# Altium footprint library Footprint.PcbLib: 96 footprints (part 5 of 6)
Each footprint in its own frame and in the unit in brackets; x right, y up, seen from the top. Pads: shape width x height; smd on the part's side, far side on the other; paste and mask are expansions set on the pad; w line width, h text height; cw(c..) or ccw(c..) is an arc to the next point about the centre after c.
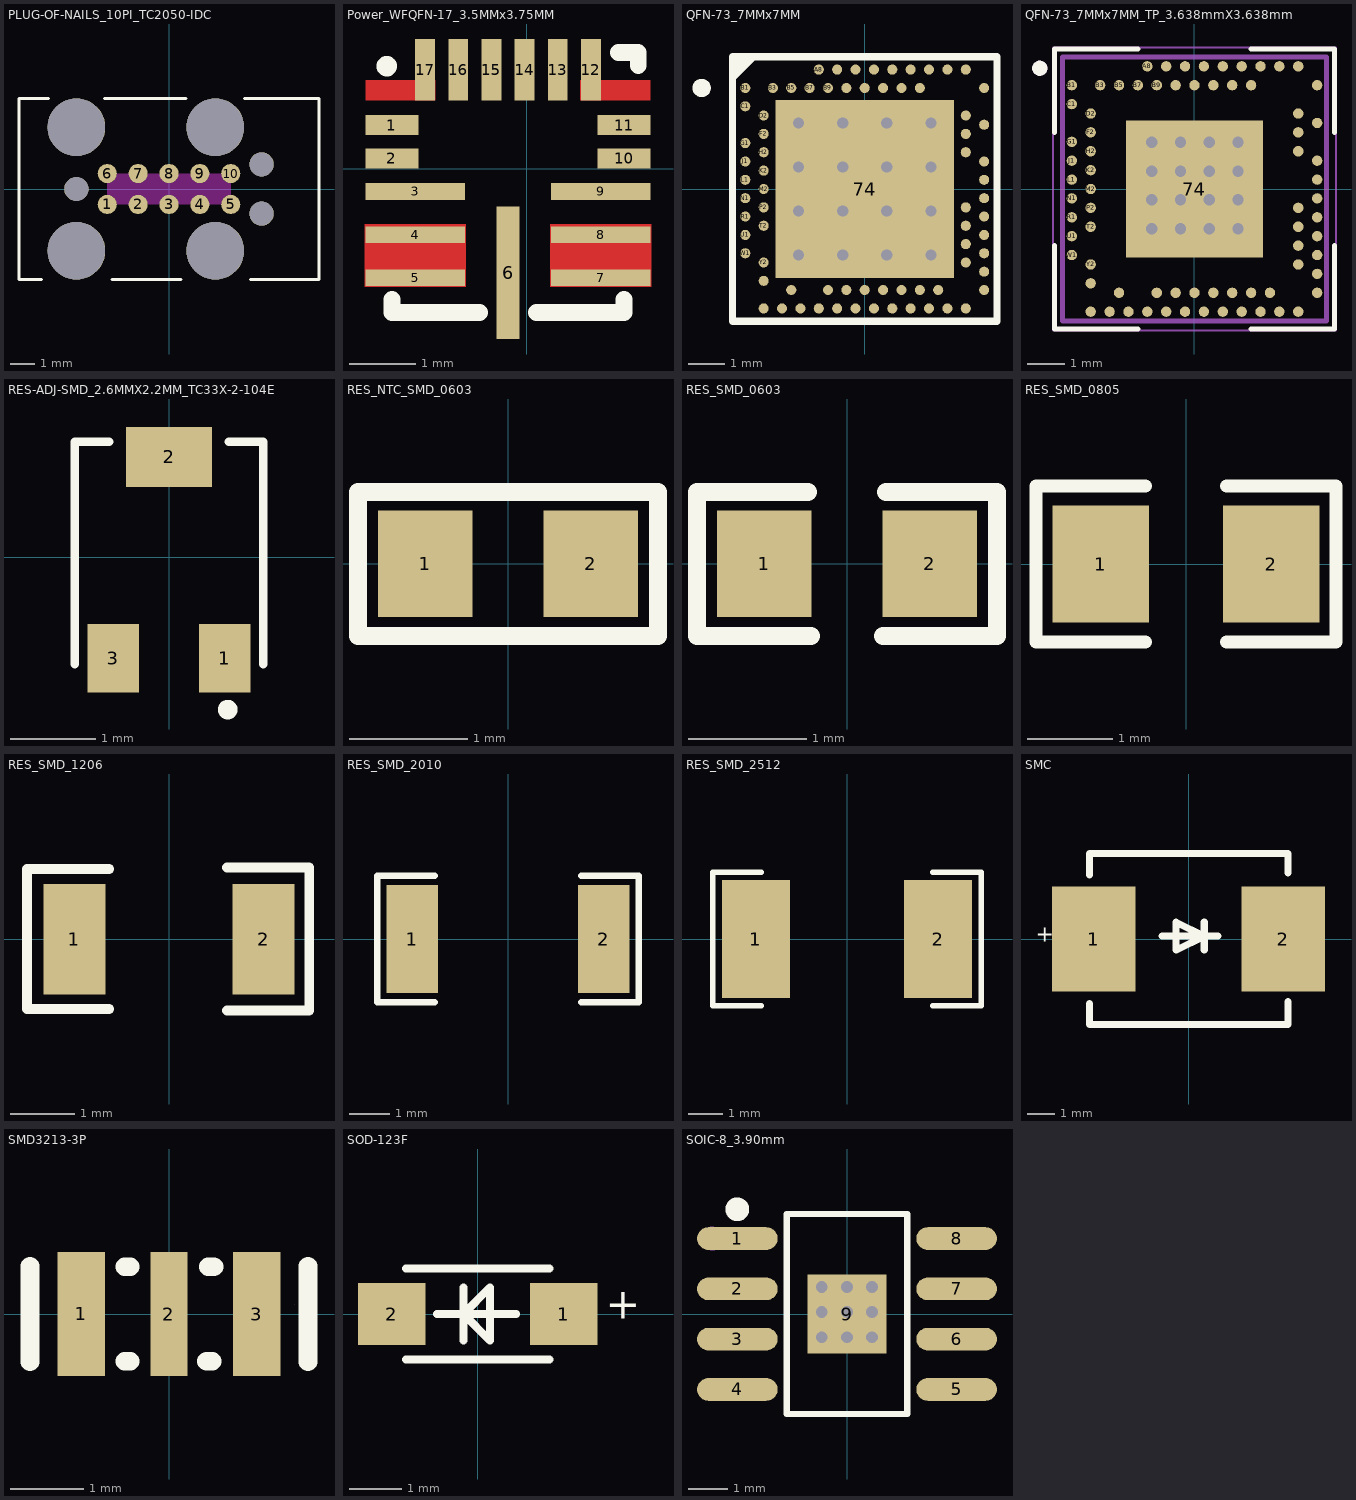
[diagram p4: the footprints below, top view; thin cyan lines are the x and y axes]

## PLUG-OF-NAILS_10PI_TC2050-IDC [mil]
pads (17):
  round 31 smd paste-39.37: 1(-100,-25) 2(-50,-25) 3(0,-25) 4(50,-25) 5(100,-25) 6(-100,25) 7(-50,25) 8(0,25) 9(50,25) 10(100,25)
  round 93.5 hole 93.5 unplated: ""(-150,-100) ""(-150,100) ""(75,-100) ""(75,100)
  round 39 hole 39 unplated: ""(-150,0) ""(150,-39.96) ""(150,39.96)
Top Overlay:
  lines w5: -206.69,-146.77 -242.91,-146.77 -242.91,146.77 -194.88,146.77 ; -104.33,146.77 27.56,146.77 ; -92.52,-146.77 19.68,-146.77 ; 122.05,146.77 242.91,146.77 242.91,-146.77 131.89,-146.77
Keep-Out Layer:
  drawing of 17 lines, arcs and shapes, not listed

## Power_WFQFN-17_3.5MMx3.75MM [mm]
pads (17):
  rect 0.8x0.3 smd paste+0 mask+0.05: 1(-2.029,0.66) 2(-2.029,0.16) 10(1.471,0.16) 11(1.471,0.66)
  rect 1.5x0.25 smd paste+0 mask+0.05: 3(-1.679,-0.34) 4(-1.679,-0.99) 5(-1.679,-1.64) 7(1.121,-1.64) 8(1.121,-0.99) 9(1.121,-0.34)
  rect 0.35x2 smd paste+0 mask+0.05: 6(-0.279,-1.565)
  rect 0.3x0.925 smd paste+0 mask+0.05: 12(0.971,1.497) 13(0.471,1.497) 14(-0.029,1.497) 15(-0.529,1.497) 16(-1.029,1.497) 17(-1.529,1.497)
Top Layer:
  region: 0.356,-0.834 1.88,-0.834 1.88,-1.778 0.356,-1.778
  region: -2.438,-0.834 -0.914,-0.834 -0.914,-1.778 -2.438,-1.778
  region: 0.813,1.338 1.866,1.338 1.866,1.038 0.813,1.038
  region: -2.424,1.338 -1.374,1.338 -1.374,1.038 -2.424,1.038
Top Overlay:
  circle w0.254: c-2.108,1.549 r0.027
  lines w0.254: -2.029,-1.965 -2.029,-2.165 -0.711,-2.165 ; 0.152,-2.165 1.471,-2.165 1.471,-1.965 ; 1.386,1.758 1.686,1.758 1.686,1.558
3D body "MAXIM_90-100129.step": height 0.8, standoff 0, extent -2.105,-2.204 1.495,1.646

## QFN-73_7MMx7MM [mm]
pads (90):
  rect 4.85x4.85 smd paste-5 mask+0.05: 74(0,0)
  round 0.275 smd paste+0.012 mask+0.05: A8(-1.25,3.25) A10(-0.75,3.25) A12(-0.25,3.25) A14(0.25,3.25) A16(0.75,3.25) A18(1.25,3.25) A20(1.75,3.25) A22(2.25,3.25) A23(2.75,3.25) AA24(3.25,-2.25) AB2(-2.75,-2.5) AC5(-2,-2.75) AC9(-1,-2.75) AC11(-0.5,-2.75) AC13(0,-2.75) AC15(0.5,-2.75) AC17(1,-2.75) AC19(1.5,-2.75) AC21(2,-2.75) AC24(3.25,-2.75) AD2(-2.75,-3.25) AD4(-2.25,-3.25) AD6(-1.75,-3.25) AD8(-1.25,-3.25) AD10(-0.75,-3.25) AD12(-0.25,-3.25) AD14(0.25,-3.25) AD16(0.75,-3.25) AD18(1.25,-3.25) AD20(1.75,-3.25) AD22(2.25,-3.25) AD23(2.75,-3.25) B1(-3.25,2.75) B3(-2.5,2.75) B5(-2,2.75) B7(-1.5,2.75) B9(-1,2.75) B11(-0.5,2.75) B13(0,2.75) B15(0.5,2.75) B17(1,2.75) B19(1.5,2.75) B24(3.25,2.75) C1(-3.25,2.25) D2(-2.75,2) D23(2.75,2) E24(3.25,1.75) F2(-2.75,1.5) F23(2.75,1.5) G1(-3.25,1.25) H2(-2.75,1) H23(2.75,1) J1(-3.25,0.75) J24(3.25,0.75) K2(-2.75,0.5) L1(-3.25,0.25) L24(3.25,0.25) M2(-2.75,0) N1(-3.25,-0.25) N24(3.25,-0.25) P2(-2.75,-0.5) P23(2.75,-0.5) R1(-3.25,-0.75) R24(3.25,-0.75) T2(-2.75,-1) T23(2.75,-1) U1(-3.25,-1.25) U24(3.25,-1.25) V23(2.75,-1.5) W1(-3.25,-1.75) W24(3.25,-1.75) Y2(-2.75,-2) Y23(2.75,-2)
  rrect50% 0.94x0.94 on Top Paste: ""(-1.71,-1.71) ""(-1.71,-0.57) ""(-1.71,0.57) ""(-1.71,1.71) ""(-0.57,-1.71) ""(-0.57,-0.57) ""(-0.57,0.57) ""(-0.57,1.71) ""(0.57,-1.71) ""(0.57,-0.57) ""(0.57,0.57) ""(0.57,1.71) ""(1.71,-1.71) ""(1.71,-0.57) ""(1.71,0.57) ""(1.71,1.71)
via 1.8,-1.8 diameter 0.61 hole 0.305
via 0.6,-1.8 diameter 0.61 hole 0.305
via -0.6,-1.8 diameter 0.61 hole 0.305
via -1.8,-1.8 diameter 0.61 hole 0.305
via 1.8,-0.6 diameter 0.61 hole 0.305
via 0.6,-0.6 diameter 0.61 hole 0.305
via -0.6,-0.6 diameter 0.61 hole 0.305
via -1.8,-0.6 diameter 0.61 hole 0.305
via 1.8,0.6 diameter 0.61 hole 0.305
via 0.6,0.6 diameter 0.61 hole 0.305
via -0.6,0.6 diameter 0.61 hole 0.305
via -1.8,0.6 diameter 0.61 hole 0.305
via 1.8,1.8 diameter 0.61 hole 0.305
via 0.6,1.8 diameter 0.61 hole 0.305
via -0.6,1.8 diameter 0.61 hole 0.305
via -1.8,1.8 diameter 0.61 hole 0.305
Top Overlay:
  circle w0.25: c-4.44,2.75 r0.125
  region: -3,3.5 -3.5,3 -3.5,3.5
  lines w0.2: -3.6,-3.6 3.6,-3.6 3.6,3.6 -3.6,3.6 -3.6,-3.6
3D body "LGA88C25P25X25_700X700X85.step": height 0.85, standoff 0, extent -3.55,-3.55 3.55,3.55

## QFN-73_7MMx7MM_TP_3.638mmX3.638mm [mm]
pads (74):
  rect 3.638x3.638 smd mask-0.01: 74(0,0)
  round 0.275 smd paste-1 mask+0: A8(-1.25,3.25) A10(-0.75,3.25) A12(-0.25,3.25) A14(0.25,3.25) A16(0.75,3.25) A18(1.25,3.25) A20(1.75,3.25) A22(2.25,3.25) A23(2.75,3.25) AA24(3.25,-2.25) AB2(-2.75,-2.5) AC5(-2,-2.75) AC9(-1,-2.75) AC11(-0.5,-2.75) AC13(0,-2.75) AC15(0.5,-2.75) AC17(1,-2.75) AC19(1.5,-2.75) AC21(2,-2.75) AC24(3.25,-2.75) AD2(-2.75,-3.25) AD4(-2.25,-3.25) AD6(-1.75,-3.25) AD8(-1.25,-3.25) AD10(-0.75,-3.25) AD12(-0.25,-3.25) AD14(0.25,-3.25) AD16(0.75,-3.25) AD18(1.25,-3.25) AD20(1.75,-3.25) AD22(2.25,-3.25) AD23(2.75,-3.25) B1(-3.25,2.75) B3(-2.5,2.75) B5(-2,2.75) B7(-1.5,2.75) B9(-1,2.75) B11(-0.5,2.75) B13(0,2.75) B15(0.5,2.75) B17(1,2.75) B19(1.5,2.75) B24(3.25,2.75) C1(-3.25,2.25) D2(-2.75,2) D23(2.75,2) E24(3.25,1.75) F2(-2.75,1.5) F23(2.75,1.5) G1(-3.25,1.25) H2(-2.75,1) H23(2.75,1) J1(-3.25,0.75) J24(3.25,0.75) K2(-2.75,0.5) L1(-3.25,0.25) L24(3.25,0.25) M2(-2.75,0) N1(-3.25,-0.25) N24(3.25,-0.25) P2(-2.75,-0.5) P23(2.75,-0.5) R1(-3.25,-0.75) R24(3.25,-0.75) T2(-2.75,-1) T23(2.75,-1) U1(-3.25,-1.25) U24(3.25,-1.25) V23(2.75,-1.5) W1(-3.25,-1.75) W24(3.25,-1.75) Y2(-2.75,-2) Y23(2.75,-2)
via -1.132,1.235 diameter 0.5 hole 0.3
via -1.132,0.473 diameter 0.5 hole 0.3
via -1.132,-0.289 diameter 0.5 hole 0.3
via -1.132,-1.051 diameter 0.5 hole 0.3
via -0.37,-1.051 diameter 0.5 hole 0.3
via -0.37,-0.289 diameter 0.5 hole 0.3
via -0.37,0.473 diameter 0.5 hole 0.3
via -0.37,1.235 diameter 0.5 hole 0.3
via 0.392,1.235 diameter 0.5 hole 0.3
via 0.392,0.473 diameter 0.5 hole 0.3
via 0.392,-0.289 diameter 0.5 hole 0.3
via 0.392,-1.051 diameter 0.5 hole 0.3
via 1.154,-1.051 diameter 0.5 hole 0.3
via 1.154,-0.289 diameter 0.5 hole 0.3
via 1.154,0.473 diameter 0.5 hole 0.3
via 1.154,1.235 diameter 0.5 hole 0.3
Top Overlay:
  circle w0.2: c-4.1,3.2 r0.1
  lines w0.127: -3.707,-1.5 -3.708,-3.707 -1.5,-3.707 ; -3.708,1.5 -3.708,3.708 -1.5,3.708 ; 1.5,-3.707 3.708,-3.707 3.708,-1.5 ; 1.5,3.708 3.708,3.708 3.707,1.5
Top Paste:
  circle w0.143: c-1.25,3.25 r0.072
  circle w0.143: c-0.75,3.25 r0.072
  circle w0.143: c-0.25,3.25 r0.072
  circle w0.143: c0.25,3.25 r0.072
  circle w0.143: c0.75,3.25 r0.072
  circle w0.143: c1.25,3.25 r0.072
  circle w0.143: c1.75,3.25 r0.072
  circle w0.143: c2.25,3.25 r0.072
  circle w0.143: c2.75,3.25 r0.072
  circle w0.143: c-2.5,2.75 r0.072
  circle w0.143: c-2,2.75 r0.072
  circle w0.143: c-1.5,2.75 r0.072
  circle w0.143: c-1,2.75 r0.072
  circle w0.143: c-0.5,2.75 r0.072
  circle w0.143: c0,2.75 r0.072
  circle w0.143: c0.5,2.75 r0.072
  circle w0.143: c1,2.75 r0.072
  circle w0.143: c1.5,2.75 r0.072
  circle w0.143: c-3.25,2.75 r0.072
  circle w0.143: c3.25,2.75 r0.072
  circle w0.143: c3.25,1.75 r0.072
  circle w0.143: c2.75,2 r0.072
  circle w0.143: c2.75,1.5 r0.072
  circle w0.143: c2.75,1 r0.072
  circle w0.143: c3.25,0.75 r0.072
  circle w0.143: c3.25,0.25 r0.072
  circle w0.143: c3.25,-0.25 r0.072
  circle w0.143: c3.25,-0.75 r0.072
  circle w0.143: c3.25,-1.25 r0.072
  circle w0.143: c3.25,-1.75 r0.072
  circle w0.143: c3.25,-2.25 r0.072
  circle w0.143: c3.25,-2.75 r0.072
  circle w0.143: c2.75,-2 r0.072
  circle w0.143: c2.75,-1.5 r0.072
  circle w0.143: c2.75,-1 r0.072
  circle w0.143: c2.75,-0.5 r0.072
  circle w0.143: c-3.25,2.25 r0.072
  circle w0.143: c-3.25,1.25 r0.072
  circle w0.143: c-3.25,0.75 r0.072
  circle w0.143: c-3.25,0.25 r0.072
  circle w0.143: c-3.25,-0.25 r0.072
  circle w0.143: c-3.25,-0.75 r0.072
  circle w0.143: c-3.25,-1.25 r0.072
  circle w0.143: c-3.25,-1.75 r0.072
  circle w0.143: c-2.75,2 r0.072
  circle w0.143: c-2.75,1.5 r0.072
  circle w0.143: c-2.75,1 r0.072
  circle w0.143: c-2.75,0.5 r0.072
  circle w0.143: c-2.75,0 r0.072
  circle w0.143: c-2.75,-0.5 r0.072
  circle w0.143: c-2.75,-1 r0.072
  circle w0.143: c-2.75,-2 r0.072
  circle w0.143: c-2.75,-2.5 r0.072
  circle w0.143: c-2.75,-3.25 r0.072
  circle w0.143: c-2.25,-3.25 r0.072
  circle w0.143: c-1.75,-3.25 r0.072
  circle w0.143: c-1.25,-3.25 r0.072
  circle w0.143: c-2,-2.75 r0.072
  circle w0.143: c-1,-2.75 r0.072
  circle w0.143: c-0.75,-3.25 r0.072
  circle w0.143: c-0.25,-3.25 r0.072
  circle w0.143: c0.25,-3.25 r0.072
  circle w0.143: c0.75,-3.25 r0.072
  circle w0.143: c1.25,-3.25 r0.072
  circle w0.143: c1.75,-3.25 r0.072
  circle w0.143: c2.25,-3.25 r0.072
  circle w0.143: c2.75,-3.25 r0.072
  circle w0.143: c2,-2.75 r0.072
  circle w0.143: c1.5,-2.75 r0.072
  circle w0.143: c1,-2.75 r0.072
  circle w0.143: c0.5,-2.75 r0.072
  circle w0.143: c0,-2.75 r0.072
  circle w0.143: c-0.5,-2.75 r0.072
Top Solder:
  circle w0.162: c-1.25,3.25 r0.081
  circle w0.162: c-0.75,3.25 r0.081
  circle w0.162: c-0.25,3.25 r0.081
  circle w0.162: c0.25,3.25 r0.081
  circle w0.162: c0.75,3.25 r0.081
  circle w0.162: c1.25,3.25 r0.081
  circle w0.162: c1.75,3.25 r0.081
  circle w0.162: c2.25,3.25 r0.081
  circle w0.162: c2.75,3.25 r0.081
  circle w0.162: c-2.5,2.75 r0.081
  circle w0.162: c-2,2.75 r0.081
  circle w0.162: c-1.5,2.75 r0.081
  circle w0.162: c-1,2.75 r0.081
  circle w0.162: c-0.5,2.75 r0.081
  circle w0.162: c0,2.75 r0.081
  circle w0.162: c0.5,2.75 r0.081
  circle w0.162: c1,2.75 r0.081
  circle w0.162: c1.5,2.75 r0.081
  circle w0.162: c-3.25,2.75 r0.081
  circle w0.162: c3.25,2.75 r0.081
  circle w0.162: c-3.25,2.25 r0.081
  circle w0.162: c-3.25,1.25 r0.081
  circle w0.162: c-3.25,0.75 r0.081
  circle w0.162: c-3.25,0.25 r0.081
  circle w0.162: c-3.25,-0.25 r0.081
  circle w0.162: c-3.25,-0.75 r0.081
  circle w0.162: c-3.25,-1.25 r0.081
  circle w0.162: c-3.25,-1.75 r0.081
  circle w0.162: c-2.75,-2 r0.081
  circle w0.162: c-2.75,-1 r0.081
  circle w0.162: c-2.75,-0.5 r0.081
  circle w0.162: c-2.75,0 r0.081
  circle w0.162: c-2.75,0.5 r0.081
  circle w0.162: c-2.75,1 r0.081
  circle w0.162: c-2.75,1.5 r0.081
  circle w0.162: c-2.75,2 r0.081
  circle w0.162: c3.25,1.75 r0.081
  circle w0.162: c2.75,2 r0.081
  circle w0.162: c2.75,1.5 r0.081
  circle w0.162: c2.75,1 r0.081
  circle w0.162: c3.25,0.75 r0.081
  circle w0.162: c3.25,0.25 r0.081
  circle w0.162: c3.25,-0.25 r0.081
  circle w0.162: c2.75,-0.5 r0.081
  circle w0.162: c2.75,-1 r0.081
  circle w0.162: c3.25,-0.75 r0.081
  circle w0.162: c3.25,-1.25 r0.081
  circle w0.162: c3.25,-1.75 r0.081
  circle w0.162: c2.75,-1.5 r0.081
  circle w0.162: c2.75,-2 r0.081
  circle w0.162: c3.25,-2.25 r0.081
  circle w0.162: c3.25,-2.75 r0.081
  circle w0.162: c2.75,-3.25 r0.081
  circle w0.162: c2.25,-3.25 r0.081
  circle w0.162: c1.75,-3.25 r0.081
  circle w0.162: c1.25,-3.25 r0.081
  circle w0.162: c0.75,-3.25 r0.081
  circle w0.162: c0.25,-3.25 r0.081
  circle w0.162: c-0.25,-3.25 r0.081
  circle w0.162: c-0.75,-3.25 r0.081
  circle w0.162: c-1.25,-3.25 r0.081
  circle w0.162: c-1.75,-3.25 r0.081
  circle w0.162: c-2.25,-3.25 r0.081
  circle w0.162: c-2.75,-3.25 r0.081
  circle w0.162: c-2,-2.75 r0.081
  circle w0.162: c-1,-2.75 r0.081
  circle w0.162: c-0.5,-2.75 r0.081
  circle w0.162: c0,-2.75 r0.081
  circle w0.162: c0.5,-2.75 r0.081
  circle w0.162: c1,-2.75 r0.081
  circle w0.162: c1.5,-2.75 r0.081
  circle w0.162: c2,-2.75 r0.081
  circle w0.162: c-2.75,-2.5 r0.081
Mechanical 13:
  circle w0.2: c-4.1,3.2 r0.1
  lines w0.127: -3.5,-3.5 3.5,-3.5 3.5,3.5 -3.5,3.5 -3.5,-3.5
Mechanical 15:
  lines w0.05: -3.75,-3.75 3.75,-3.75 3.75,3.75 -3.75,3.75 -3.75,-3.75
3D body "LGA88C25P25X25_700X700X85.step": height 0.85, standoff 0, extent -3.55,-3.55 3.55,3.55

## RES-ADJ-SMD_2.6MMX2.2MM_TC33X-2-104E [mm]
pads (3):
  rect 0.6x0.8 smd mask+0.04: 1(0.65,-1.175) 3(-0.65,-1.175)
  rect 1x0.7 smd mask+0.04: 2(0,1.175)
Top Overlay:
  circle w0.127: c0.686,-1.778 r0.051
  lines w0.1: -1.1,-1.25 -1.1,1.35 -0.7,1.35 ; 0.7,1.35 1.1,1.35 1.1,-1.25
3D body "TC42.stp": height 0.84, standoff 0.05, extent -1.079,-1.524 1.13,1.321

## RES_NTC_SMD_0603 [mm]
pads (2):
  rect 0.8x0.9 smd paste+0 mask+0.051: 1(-0.7,0) 2(0.7,0)
Top Overlay:
  lines w0.152: -1.27,-0.611 -1.27,0.608 1.27,0.608 1.27,-0.611 -1.245,-0.611
3D body "bf_0603_part.step": height 0.8, standoff 0, extent -0.8,-0.452 0.8,0.453

## RES_SMD_0402 [mm]

## RES_SMD_0603 [mm]
pads (2):
  rect 0.8x0.9 smd paste+0 mask+0.051: 1(-0.7,0) 2(0.7,0)
Top Overlay:
  lines w0.152: -0.33,0.608 -1.27,0.608 -1.27,-0.611 -0.305,-0.611 ; 0.305,-0.611 1.27,-0.611 1.27,0.608 0.33,0.608
3D body "User Library-CR1608-0603.step": height 0.45, standoff 0, extent -0.8,-0.4 0.8,0.4

## RES_SMD_0805 [mm]
pads (2):
  rect 1.133x1.377 smd paste-100 mask+0.051: 1(-1,0) 2(1,0)
Top Overlay:
  lines w0.152: -0.476,-0.917 -1.761,-0.917 -1.761,0.917 -0.476,0.917 ; 0.476,-0.917 1.761,-0.917 1.761,0.917 0.476,0.917
3D body "ESR10EZPJ100.step": height 0.65, standoff 0, extent -1.102,-0.574 0.898,0.676

## RES_SMD_1206 [mm]
pads (2):
  rect 0.97x1.73 smd: 1(-1.48,0) 2(1.48,0)
Top Overlay:
  lines w0.152: -0.933,-1.092 -2.218,-1.092 -2.218,1.095 -0.933,1.095 ; 0.908,-1.118 2.193,-1.118 2.193,1.12 0.908,1.12
3D body "step_temp.STEP": height 0.65, standoff 0, extent -1.55,-0.8 1.55,0.8

## RES_SMD_2010 [mm]
pads (2):
  rect 1.283x2.7 smd paste-100 mask+0.051: 1(-2.391,0) 2(2.391,0)
Top Overlay:
  lines w0.152: -1.826,-1.579 -3.261,-1.579 -3.261,1.579 -1.826,1.579 ; 1.826,-1.579 3.261,-1.579 3.261,1.579 1.826,1.579
3D body "STA_CSNL201031_STP.step": height 0.89, standoff 0, extent -2.667,-1.397 2.667,1.397

## RES_SMD_2512 [mm]
pads (2):
  rect 2x3.456 smd paste-100 mask+0.051: 1(-2.667,0) 2(2.667,0)
Top Overlay:
  lines w0.152: -2.501,-1.957 -3.936,-1.957 -3.936,1.957 -2.501,1.957 ; 2.501,-1.957 3.936,-1.957 3.936,1.957 2.501,1.957
3D body "WSL25128L300FEA.step": height 0.89, standoff 0, extent -3.175,-1.587 3.175,1.588

## SMC [mm]
pads (2):
  rect 3.03x3.82 smd paste+0 mask+0.051: 1(-3.435,0) 2(3.435,0)
Top Overlay:
  lines w0.254: -3.6,-2.348 -3.6,-3.11 3.6,-3.11 3.6,-2.272 ; -3.6,2.326 -3.6,3.11 3.6,3.11 3.6,2.402 ; -0.965,0.102 1.067,0.102 ; 0.559,-0.406 0.559,0.61 0.559,0.102 ; 0.571,0.102 0.571,-0.406 0.571,0.61 ; 0.559,0.102 -0.457,0.61 -0.457,-0.406 0.559,0.102
  text "+" at -5.537,-0.305 h1
3D body "B550C-13-F.step": height 2.5, standoff 0, extent -3.64,-2.927 4.3,2.978

## SMD3213-3P [mm]
pads (3):
  rect 0.65x1.7 smd: 1(-1.2,0) 3(1.2,0)
  rect 0.5x1.7 smd: 2(0,0)
Top Overlay:
  lines w0.254: -1.9,-0.65 -1.9,0.65 ; -0.605,-0.647 -0.528,-0.647 ; -0.605,0.649 -0.528,0.649 ; 0.513,-0.647 0.589,-0.647 ; 0.538,0.649 0.615,0.649 ; 1.9,-0.65 1.9,0.65
Mechanical 15:
  lines w0.003: 1.714,0.127 1.715,0.127
3D body "SMD3213-3P.STEP": height 1, standoff 0, extent -1.6,-0.65 1.6,0.65

## SOD-123F [mm]
pads (2):
  rect 1.3x1.2 smd paste+0 mask+0.051: 1(1.65,0) 2(-1.65,0)
Top Overlay:
  lines w0.15: -0.782,0 0.742,0 ; -0.274,-0.508 -0.274,0.508 ; -0.274,-0.254 -0.274,0.254 ; -0.274,0 0.234,0.508 0.234,-0.508 -0.274,0
  lines w0.152: -1.376,-0.876 1.376,-0.876 ; -1.376,0.876 1.376,0.876
  text "+" at 2.464,-0.279 h1
3D body "1N4148W.STEP": height 1.1, standoff 0.1, extent -1.849,-0.838 1.951,0.762

## SOIC-8_3.90mm [mm]
pads (9):
  oval 2.038x0.574 smd paste+0 mask+0.051: 1(-2.769,1.905) 2(-2.769,0.635) 3(-2.769,-0.635) 4(-2.769,-1.905) 5(2.769,-1.905) 6(2.769,-0.635) 7(2.769,0.635) 8(2.769,1.905)
  rect 2x2 smd paste+0 mask+0.051: 9(0,0)
via -0.638,0.683 diameter 0.5 hole 0.3
via -0.003,0.683 diameter 0.5 hole 0.3
via 0.632,0.683 diameter 0.5 hole 0.3
via 0.632,0.048 diameter 0.5 hole 0.3
via -0.003,0.048 diameter 0.5 hole 0.3
via -0.638,0.048 diameter 0.5 hole 0.3
via -0.638,-0.587 diameter 0.5 hole 0.3
via -0.003,-0.587 diameter 0.5 hole 0.3
via 0.632,-0.587 diameter 0.5 hole 0.3
Top Overlay:
  circle w0.3: c-2.769,2.644 r0.15
  lines w0.152: -1.521,-2.526 -1.521,2.526 1.521,2.526 1.521,-2.526 -1.521,-2.526
Mechanical 15:
  circle w0.3: c-3.4,1.905 r0.15
3D body "RT8289GSP.step": height 1.75, standoff 0, extent -2.998,-2.451 2.998,2.451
